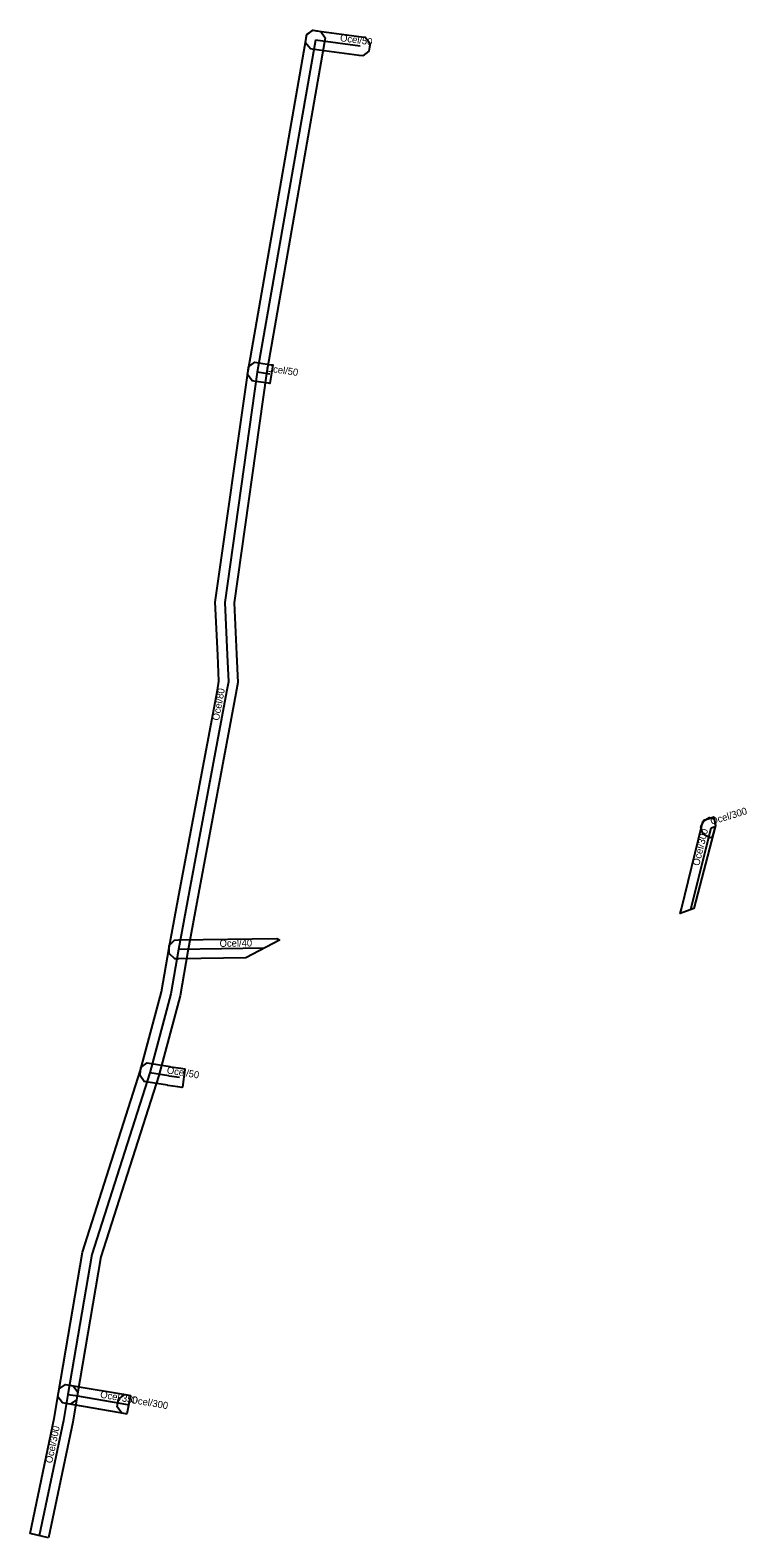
# Model space of a CAD drawing. Extents: x -444520 to -444444, y -1121189 to -1121028.
import ezdxf

# ---------------------------------------------------------------- set-up
doc = ezdxf.new("R2010")
doc.units = 0
for name, color, linetype in [('1', 7, 'Continuous'), ('14', 7, 'Continuous'), ('20', 7, 'Continuous')]:
    doc.layers.add(name, color=color, linetype=linetype)

msp = doc.modelspace()

# ---------------------------------------------------------------- linework, layer by layer
at = {"layer": '1'}
for points in [[(-444488.9, -1121029.27), (-444488.97, -1121029.67), (-444495.14, -1121064.93), (-444498.58, -1121089.29), (-444498.33, -1121094.75), (-444498.19, -1121097.74), (-444498.41, -1121098.92), (-444502.37, -1121120.15), (-444503.51, -1121126.27), (-444504.33, -1121131.03), (-444506.6, -1121139.5), (-444512.75, -1121158.74), (-444515.27, -1121173.53), (-444515.34, -1121173.94), (-444516.02, -1121174.42), (-444516.42, -1121174.35), (-444516.83, -1121174.28), (-444517.31, -1121173.61), (-444517.24, -1121173.2), (-444514.7, -1121158.27), (-444508.52, -1121138.93), (-444506.29, -1121130.6), (-444505.48, -1121125.91), (-444504.34, -1121119.78), (-444500.37, -1121098.56), (-444500.2, -1121097.6), (-444500.33, -1121094.85), (-444500.59, -1121089.2), (-444497.11, -1121064.62), (-444490.94, -1121029.33), (-444490.86, -1121028.92), (-444490.19, -1121028.45), (-444489.78, -1121028.52), (-444489.37, -1121028.59)], [(-444484.91, -1121031.17), (-444485.32, -1121031.12), (-444490.08, -1121030.49), (-444490.49, -1121030.44), (-444491, -1121029.78), (-444490.94, -1121029.37), (-444490.89, -1121028.96), (-444490.23, -1121028.46), (-444489.82, -1121028.51), (-444485.06, -1121029.14), (-444484.65, -1121029.19), (-444484.15, -1121029.85), (-444484.2, -1121030.26), (-444484.26, -1121030.67)], [(-444494.64, -1121063.99), (-444494.47, -1121064.01), (-444494.79, -1121065.99), (-444494.94, -1121065.96), (-444496.27, -1121065.77), (-444496.68, -1121065.71), (-444497.17, -1121065.04), (-444497.11, -1121064.63), (-444497.05, -1121064.22), (-444496.39, -1121063.73), (-444495.98, -1121063.79)], [(-444449.76, -1121121.75), (-444451.2, -1121122.3), (-444451.07, -1121121.78), (-444448.89, -1121112.93), (-444448.79, -1121112.52), (-444448.09, -1121112.09), (-444447.68, -1121112.19), (-444447.58, -1121112.22), (-444447.46, -1121112.93)], [(-444447.46, -1121112.93), (-444447.79, -1121114.17), (-444448.03, -1121114.24), (-444448.76, -1121113.85), (-444448.88, -1121113.46), (-444449, -1121113.06), (-444448.61, -1121112.33), (-444448.22, -1121112.21), (-444447.61, -1121112.02)], [(-444494.06, -1121124.95), (-444493.77, -1121125.13), (-444497.34, -1121126.99), (-444504.48, -1121127.09), (-444504.9, -1121127.1), (-444505.49, -1121126.52), (-444505.49, -1121126.1), (-444505.5, -1121125.69), (-444504.92, -1121125.1), (-444504.51, -1121125.09)], [(-444503.82, -1121138.82), (-444504.09, -1121140.73), (-444504.15, -1121140.77), (-444504.56, -1121140.71), (-444505.64, -1121140.54), (-444505.67, -1121140.53), (-444507.72, -1121140.2), (-444508.13, -1121140.14), (-444508.62, -1121139.47), (-444508.55, -1121139.06), (-444508.49, -1121138.65), (-444507.82, -1121138.16), (-444507.41, -1121138.23), (-444505.37, -1121138.55), (-444505.34, -1121138.56), (-444504.25, -1121138.73), (-444503.84, -1121138.8)], [(-444518.31, -1121188.61), (-444520.26, -1121188.16), (-444517.71, -1121175.94), (-444517.24, -1121173.2), (-444517.17, -1121172.79), (-444516.49, -1121172.31), (-444516.09, -1121172.38), (-444515.68, -1121172.45), (-444515.2, -1121173.13), (-444515.27, -1121173.53), (-444515.74, -1121176.31)], [(-444509.6, -1121173.49), (-444509.99, -1121175.45), (-444510.13, -1121175.43), (-444510.69, -1121175.33), (-444515.62, -1121174.49), (-444516.42, -1121174.35), (-444516.83, -1121174.28), (-444517.31, -1121173.61), (-444517.24, -1121173.2), (-444517.17, -1121172.79), (-444516.49, -1121172.31), (-444516.09, -1121172.38), (-444515.28, -1121172.52), (-444510.35, -1121173.36), (-444509.79, -1121173.46)], [(-444509.6, -1121173.49), (-444509.99, -1121175.45), (-444510.12, -1121175.43), (-444510.53, -1121175.36), (-444511.01, -1121174.68), (-444510.94, -1121174.28), (-444510.87, -1121173.87), (-444510.2, -1121173.39), (-444509.79, -1121173.46)]]:
    msp.add_lwpolyline(points, close=True, dxfattribs=at)
at = {"layer": '14'}
for points in [[(-444489.95, -1121029.5), (-444496.13, -1121064.78), (-444499.59, -1121089.24), (-444499.33, -1121094.8), (-444499.19, -1121097.67), (-444499.39, -1121098.74), (-444503.35, -1121119.97), (-444504.49, -1121126.09), (-444505.31, -1121130.82), (-444507.56, -1121139.22), (-444513.72, -1121158.5), (-444516.26, -1121173.37)], [(-444485.19, -1121030.13), (-444489.95, -1121029.5)], [(-444494.79, -1121064.98), (-444496.13, -1121064.78)], [(-444450.06, -1121121.86), (-444447.92, -1121113.17)], [(-444447.92, -1121113.17), (-444447.49, -1121113.03)], [(-444495.37, -1121125.97), (-444504.49, -1121126.09)], [(-444504.4, -1121139.72), (-444505.49, -1121139.55), (-444505.52, -1121139.54), (-444507.56, -1121139.22)], [(-444516.26, -1121173.37), (-444516.73, -1121176.13), (-444519.29, -1121188.39)], [(-444516.26, -1121173.37), (-444515.45, -1121173.5), (-444510.52, -1121174.35), (-444509.96, -1121174.44)], [(-444509.96, -1121174.44), (-444509.8, -1121174.47)]]:
    msp.add_lwpolyline(points, dxfattribs=at)

# ---------------------------------------------------------------- texts
at = {"layer": '20'}
for s, rotation, p in [('Ocel/50', 352.4827, (-444487.37, -1121029.61)), ('Ocel/50', 351.6119, (-444495.26, -1121064.68)), ('Ocel/80', 79.4296, (-444500.2, -1121101.83)), ('Ocel/300', 17.0567, (-444447.86, -1121112.88)), ('Ocel/300', 76.1757, (-444449.18, -1121117.27)), ('Ocel/40', 0.7846, (-444500.13, -1121125.83)), ('Ocel/50', 350.9196, (-444505.78, -1121139.27)), ('Ocel/350', 350.306, (-444512.86, -1121173.71)), ('Ocel/300', 350.3028, (-444509.63, -1121174.27)), ('Ocel/300', 78.2008, (-444517.93, -1121180.73))]:
    msp.add_text(s, height=0.75, rotation=rotation, dxfattribs=at).set_placement(p)

doc.saveas('drawing.dxf')
